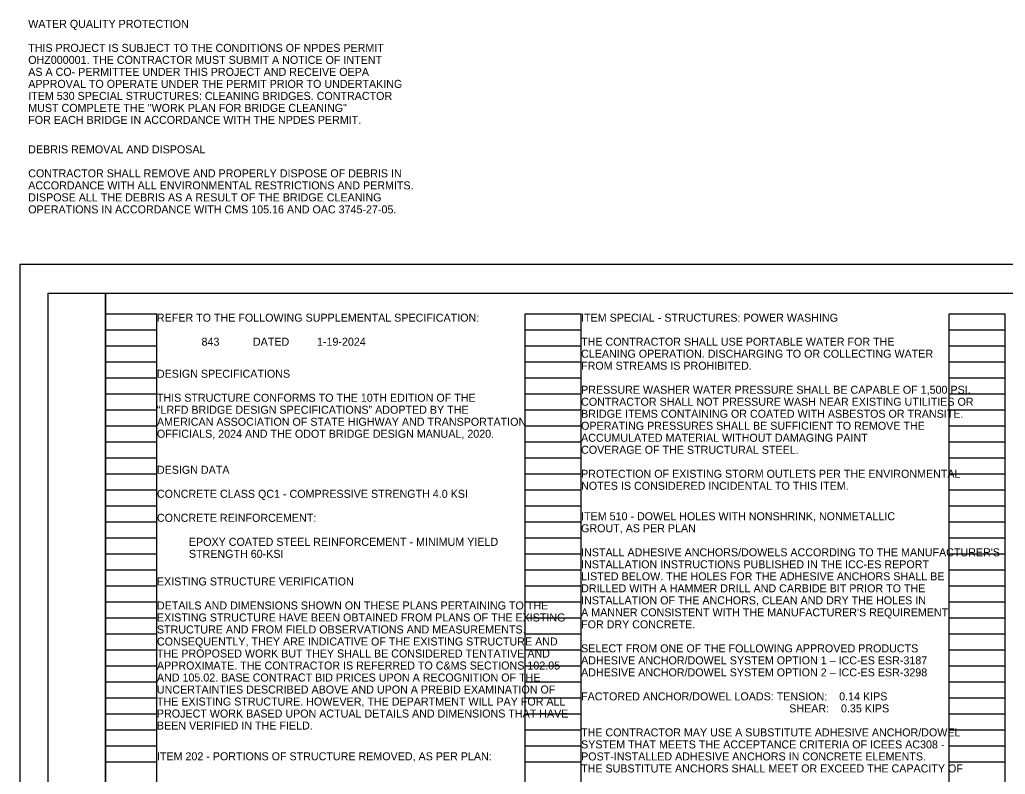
# Model space of a CAD drawing. Extents: x 0 to 34, y -2.4 to 26.3.
# Drawn here: x 0 to 17.24, y 13.08 to 26.28 of the extents above; entities that cross this region are included whole.
import ezdxf

# ---------------------------------------------------------------- set-up
doc = ezdxf.new("R2010")
doc.units = 0
for name, color, linetype in [('BR_P_Gen_Text', 7, 'Continuous'), ('SH_Border', 7, 'Continuous'), ('SH_Cut_Line', 7, 'Continuous'), ('SH_Data', 7, 'Continuous'), ('SH_Text', 7, 'Continuous')]:
    doc.layers.add(name, color=color, linetype=linetype)

msp = doc.modelspace()

# ---------------------------------------------------------------- linework, layer by layer
at = {"layer": 'SH_Border'}
for points in [[(0.5, 21.5), (1.5, 21.5), (1.5, 0.5), (0.5, 0.5)], [(1.5, 21.5), (33.5, 21.5), (33.5, 0.5), (1.5, 0.5)]]:
    msp.add_lwpolyline(points, close=True, dxfattribs=at)
at = {"layer": 'SH_Cut_Line'}
msp.add_lwpolyline([(0, 0), (34, 0), (34, 22), (0, 22)], close=True, dxfattribs=at)
at = {"layer": 'SH_Data'}
for p, q in [((1.5, 0.98), (1.5, 21.14)), ((1.5, 21.14), (2.4, 21.14)), ((2.4, 0.98), (2.4, 21.14)), ((8.84, 0.98), (8.84, 21.14)), ((8.84, 21.14), (9.82, 21.14)), ((9.82, 0.98), (9.82, 21.14)), ((16.26, 0.98), (16.26, 21.14)), ((16.26, 21.14), (17.24, 21.14)), ((17.24, 0.98), (17.24, 21.14)), ((1.5, 20.86), (2.4, 20.86)), ((8.84, 20.86), (9.82, 20.86)), ((16.26, 20.86), (17.24, 20.86)), ((1.5, 20.58), (2.4, 20.58)), ((8.84, 20.58), (9.82, 20.58)), ((16.26, 20.58), (17.24, 20.58)), ((1.5, 20.3), (2.4, 20.3)), ((8.84, 20.3), (9.82, 20.3)), ((16.26, 20.3), (17.24, 20.3)), ((1.5, 20.02), (2.4, 20.02)), ((8.84, 20.02), (9.82, 20.02)), ((16.26, 20.02), (17.24, 20.02)), ((1.5, 19.74), (2.4, 19.74)), ((8.84, 19.74), (9.82, 19.74)), ((16.26, 19.74), (17.24, 19.74)), ((1.5, 19.46), (2.4, 19.46)), ((8.84, 19.46), (9.82, 19.46)), ((16.26, 19.46), (17.24, 19.46)), ((1.5, 19.18), (2.4, 19.18)), ((8.84, 19.18), (9.82, 19.18)), ((16.26, 19.18), (17.24, 19.18)), ((1.5, 18.9), (2.4, 18.9)), ((8.84, 18.9), (9.82, 18.9)), ((16.26, 18.9), (17.24, 18.9)), ((1.5, 18.62), (2.4, 18.62)), ((8.84, 18.62), (9.82, 18.62)), ((16.26, 18.62), (17.24, 18.62)), ((1.5, 18.34), (2.4, 18.34)), ((8.84, 18.34), (9.82, 18.34)), ((16.26, 18.34), (17.24, 18.34)), ((1.5, 18.06), (2.4, 18.06)), ((8.84, 18.06), (9.82, 18.06)), ((16.26, 18.06), (17.24, 18.06)), ((1.5, 17.78), (2.4, 17.78)), ((8.84, 17.78), (9.82, 17.78)), ((16.26, 17.78), (17.24, 17.78)), ((1.5, 17.5), (2.4, 17.5)), ((8.84, 17.5), (9.82, 17.5)), ((16.26, 17.5), (17.24, 17.5)), ((1.5, 17.22), (2.4, 17.22)), ((8.84, 17.22), (9.82, 17.22)), ((16.26, 17.22), (17.24, 17.22)), ((1.5, 16.94), (2.4, 16.94)), ((8.84, 16.94), (9.82, 16.94)), ((16.26, 16.94), (17.24, 16.94)), ((1.5, 16.66), (2.4, 16.66)), ((8.84, 16.66), (9.82, 16.66)), ((16.26, 16.66), (17.24, 16.66)), ((1.5, 16.38), (2.4, 16.38)), ((8.84, 16.38), (9.82, 16.38)), ((16.26, 16.38), (17.24, 16.38)), ((1.5, 16.1), (2.4, 16.1)), ((8.84, 16.1), (9.82, 16.1)), ((16.26, 16.1), (17.24, 16.1)), ((1.5, 15.82), (2.4, 15.82)), ((8.84, 15.82), (9.82, 15.82)), ((16.26, 15.82), (17.24, 15.82)), ((1.5, 15.54), (2.4, 15.54)), ((8.84, 15.54), (9.82, 15.54)), ((16.26, 15.54), (17.24, 15.54)), ((1.5, 15.26), (2.4, 15.26)), ((8.84, 15.26), (9.82, 15.26)), ((16.26, 15.26), (17.24, 15.26)), ((1.5, 14.98), (2.4, 14.98)), ((8.84, 14.98), (9.82, 14.98)), ((16.26, 14.98), (17.24, 14.98)), ((1.5, 14.7), (2.4, 14.7)), ((8.84, 14.7), (9.82, 14.7)), ((16.26, 14.7), (17.24, 14.7)), ((1.5, 14.42), (2.4, 14.42)), ((8.84, 14.42), (9.82, 14.42)), ((16.26, 14.42), (17.24, 14.42)), ((1.5, 14.14), (2.4, 14.14)), ((8.84, 14.14), (9.82, 14.14)), ((16.26, 14.14), (17.24, 14.14)), ((1.5, 13.86), (2.4, 13.86)), ((8.84, 13.86), (9.82, 13.86)), ((16.26, 13.86), (17.24, 13.86)), ((1.5, 13.58), (2.4, 13.58)), ((8.84, 13.58), (9.82, 13.58)), ((16.26, 13.58), (17.24, 13.58)), ((1.5, 13.3), (2.4, 13.3)), ((8.84, 13.3), (9.82, 13.3)), ((16.26, 13.3), (17.24, 13.3))]:
    msp.add_line(p, q, dxfattribs=at)

# ---------------------------------------------------------------- texts
at = {"layer": 'BR_P_Gen_Text'}
for s, p in [('REFER TO THE FOLLOWING SUPPLEMENTAL SPECIFICATION:', (2.4, 21)), ('ITEM SPECIAL - STRUCTURES: POWER WASHING', (9.82, 21)), ('               843', (2.4, 20.58)), ('DATED', (4.08, 20.58)), ('1-19-2024', (5.2, 20.58)), ('THE CONTRACTOR SHALL USE PORTABLE WATER FOR THE ', (9.82, 20.58)), ('CLEANING OPERATION. DISCHARGING TO OR COLLECTING WATER ', (9.82, 20.37)), ('FROM STREAMS IS PROHIBITED.', (9.82, 20.16)), ('DESIGN SPECIFICATIONS', (2.4, 20.02)), ('PRESSURE WASHER WATER PRESSURE SHALL BE CAPABLE OF 1,500 PSI.', (9.82, 19.74)), ('THIS STRUCTURE CONFORMS TO THE 10TH EDITION OF THE ', (2.4, 19.6)), ('CONTRACTOR SHALL NOT PRESSURE WASH NEAR EXISTING UTILITIES OR', (9.82, 19.53)), ('“LRFD BRIDGE DESIGN SPECIFICATIONS” ADOPTED BY THE ', (2.4, 19.39)), ('AMERICAN ASSOCIATION OF STATE HIGHWAY AND TRANSPORTATION ', (2.4, 19.18)), ('BRIDGE ITEMS CONTAINING OR COATED WITH ASBESTOS OR TRANSITE. ', (9.82, 19.32)), ('OPERATING PRESSURES SHALL BE SUFFICIENT TO REMOVE THE ', (9.82, 19.11)), ('OFFICIALS, 2024 AND THE ODOT BRIDGE DESIGN MANUAL, 2020.', (2.4, 18.97)), ('ACCUMULATED MATERIAL WITHOUT DAMAGING PAINT ', (9.82, 18.9)), ('COVERAGE OF THE STRUCTURAL STEEL.', (9.82, 18.69)), ('DESIGN DATA', (2.4, 18.34)), ('PROTECTION OF EXISTING STORM OUTLETS PER THE ENVIRONMENTAL ', (9.82, 18.27)), ('NOTES IS CONSIDERED INCIDENTAL TO THIS ITEM.', (9.82, 18.06)), ('CONCRETE CLASS QC1 - COMPRESSIVE STRENGTH 4.0 KSI', (2.4, 17.92)), ('CONCRETE REINFORCEMENT:', (2.4, 17.5)), ('ITEM 510 - DOWEL HOLES WITH NONSHRINK, NONMETALLIC ', (9.82, 17.527)), ('GROUT, AS PER PLAN', (9.82, 17.317)), ('EPOXY COATED STEEL REINFORCEMENT - MINIMUM YIELD', (2.96, 17.08)), ('STRENGTH 60-KSI', (2.96, 16.87)), ("INSTALL ADHESIVE ANCHORS/DOWELS ACCORDING TO THE MANUFACTURER'S ", (9.82, 16.897)), ('INSTALLATION INSTRUCTIONS PUBLISHED IN THE ICC-ES REPORT ', (9.82, 16.687)), ('LISTED BELOW. THE HOLES FOR THE ADHESIVE ANCHORS SHALL BE ', (9.82, 16.477)), ('EXISTING STRUCTURE VERIFICATION', (2.4, 16.387)), ('DRILLED WITH A HAMMER DRILL AND CARBIDE BIT PRIOR TO THE ', (9.82, 16.267)), ('DETAILS AND DIMENSIONS SHOWN ON THESE PLANS PERTAINING TO THE ', (2.4, 15.967)), ('INSTALLATION OF THE ANCHORS, CLEAN AND DRY THE HOLES IN ', (9.82, 16.057)), ('EXISTING STRUCTURE HAVE BEEN OBTAINED FROM PLANS OF THE EXISTING ', (2.4, 15.757)), ("A MANNER CONSISTENT WITH THE MANUFACTURER'S REQUIREMENT", (9.82, 15.847)), ('STRUCTURE AND FROM FIELD OBSERVATIONS AND MEASUREMENTS. ', (2.4, 15.547)), ('FOR DRY CONCRETE.', (9.82, 15.637)), ('CONSEQUENTLY, THEY ARE INDICATIVE OF THE EXISTING STRUCTURE AND ', (2.4, 15.337)), ('SELECT FROM ONE OF THE FOLLOWING APPROVED PRODUCTS', (9.82, 15.217)), ('THE PROPOSED WORK BUT THEY SHALL BE CONSIDERED TENTATIVE AND ', (2.4, 15.127)), ('APPROXIMATE. THE CONTRACTOR IS REFERRED TO C&MS SECTIONS 102.05 ', (2.4, 14.917)), ('ADHESIVE ANCHOR/DOWEL SYSTEM OPTION 1 – ICC-ES ESR-3187 ', (9.82, 15.007)), ('AND 105.02. BASE CONTRACT BID PRICES UPON A RECOGNITION OF THE ', (2.4, 14.707)), ('ADHESIVE ANCHOR/DOWEL SYSTEM OPTION 2 – ICC-ES ESR-3298', (9.82, 14.797)), ('UNCERTAINTIES DESCRIBED ABOVE AND UPON A PREBID EXAMINATION OF ', (2.4, 14.497)), ('FACTORED ANCHOR/DOWEL LOADS: TENSION:    0.14 KIPS', (9.82, 14.377)), ('THE EXISTING STRUCTURE. HOWEVER, THE DEPARTMENT WILL PAY FOR ALL ', (2.4, 14.287)), ('PROJECT WORK BASED UPON ACTUAL DETAILS AND DIMENSIONS THAT HAVE ', (2.4, 14.077)), ('                                                                      SHEAR:    0.35 KIPS ', (9.82, 14.167)), ('BEEN VERIFIED IN THE FIELD.', (2.4, 13.867)), ('THE CONTRACTOR MAY USE A SUBSTITUTE ADHESIVE ANCHOR/DOWEL ', (9.82, 13.747)), ('SYSTEM THAT MEETS THE ACCEPTANCE CRITERIA OF ICEES AC308 -', (9.82, 13.537)), ('ITEM 202 - PORTIONS OF STRUCTURE REMOVED, AS PER PLAN:', (2.4, 13.329)), ('POST-INSTALLED ADHESIVE ANCHORS IN CONCRETE ELEMENTS. ', (9.82, 13.327)), ('THE SUBSTITUTE ANCHORS SHALL MEET OR EXCEED THE CAPACITY OF', (9.82, 13.117))]:
    msp.add_text(s, height=0.14, dxfattribs=at).set_placement(p)
at = {"layer": 'SH_Text'}
for s, p in [('WATER QUALITY PROTECTION', (0.149, 26.139)), ('THIS PROJECT IS SUBJECT TO THE CONDITIONS OF NPDES PERMIT ', (0.149, 25.719)), ('OHZ000001. THE CONTRACTOR MUST SUBMIT A NOTICE OF INTENT ', (0.149, 25.509)), ('AS A CO- PERMITTEE UNDER THIS PROJECT AND RECEIVE OEPA', (0.149, 25.299)), ('APPROVAL TO OPERATE UNDER THE PERMIT PRIOR TO UNDERTAKING ', (0.149, 25.089)), ('ITEM 530 SPECIAL STRUCTURES: CLEANING BRIDGES. CONTRACTOR ', (0.149, 24.879)), ('MUST COMPLETE THE "WORK PLAN FOR BRIDGE CLEANING" ', (0.149, 24.669)), ('FOR EACH BRIDGE IN ACCORDANCE WITH THE NPDES PERMIT.', (0.149, 24.459)), ('DEBRIS REMOVAL AND DISPOSAL', (0.149, 23.944)), ('CONTRACTOR SHALL REMOVE AND PROPERLY DISPOSE OF DEBRIS IN', (0.149, 23.524)), ('ACCORDANCE WITH ALL ENVIRONMENTAL RESTRICTIONS AND PERMITS.', (0.149, 23.314)), ('DISPOSE ALL THE DEBRIS AS A RESULT OF THE BRIDGE CLEANING', (0.149, 23.104)), ('OPERATIONS IN ACCORDANCE WITH CMS 105.16 AND OAC 3745-27-05.', (0.149, 22.894))]:
    msp.add_text(s, height=0.14, dxfattribs=at).set_placement(p)

doc.saveas('drawing.dxf')
